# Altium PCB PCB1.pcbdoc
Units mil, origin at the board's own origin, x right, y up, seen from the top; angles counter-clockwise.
Board outline 2864.75 x 3097.61 mil, 2 copper layers (Top Layer, Bottom Layer); 25 components, 23 nets, 126 pads, 0 vias.
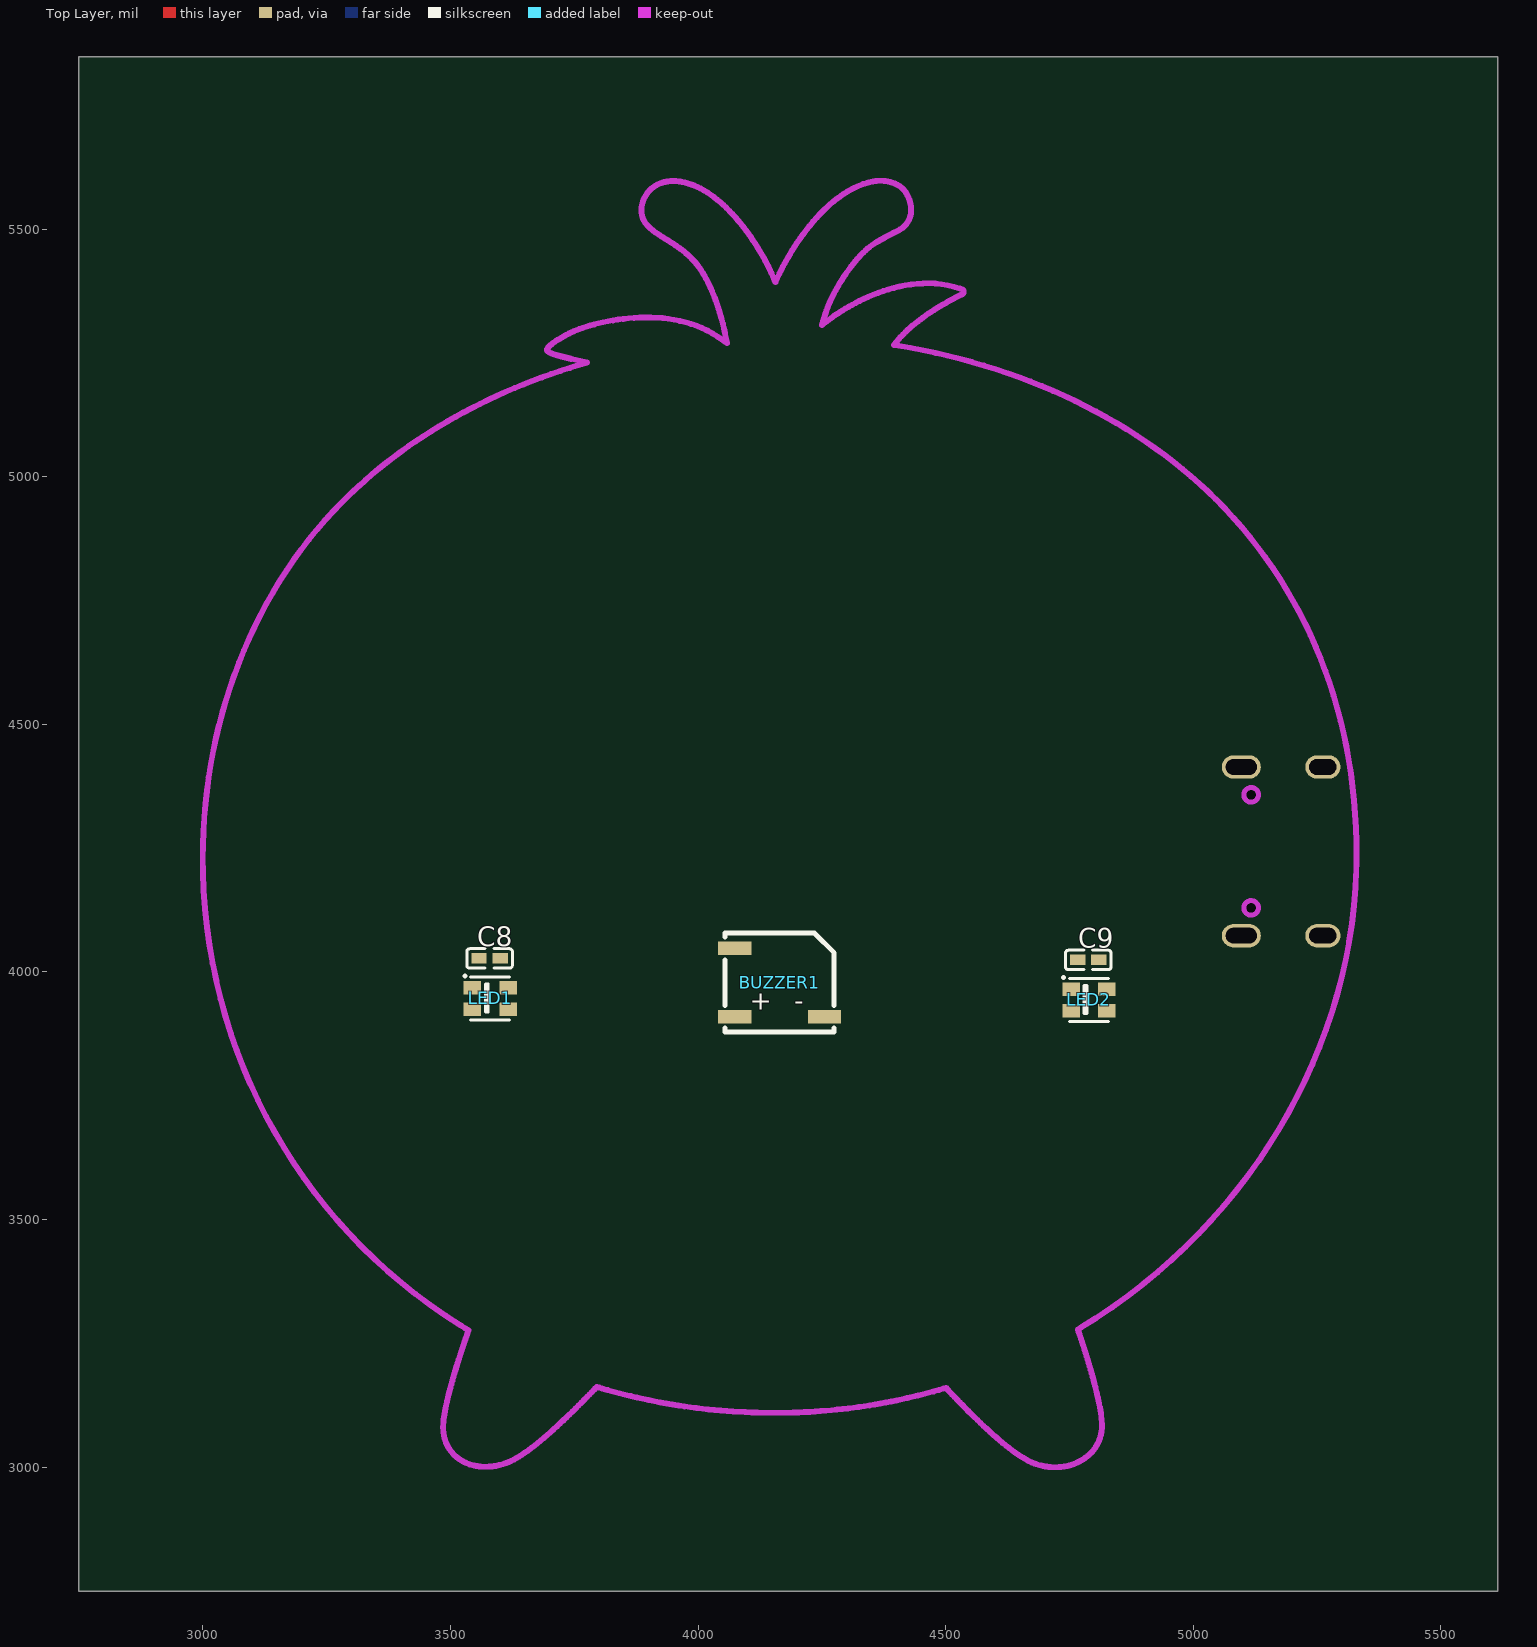
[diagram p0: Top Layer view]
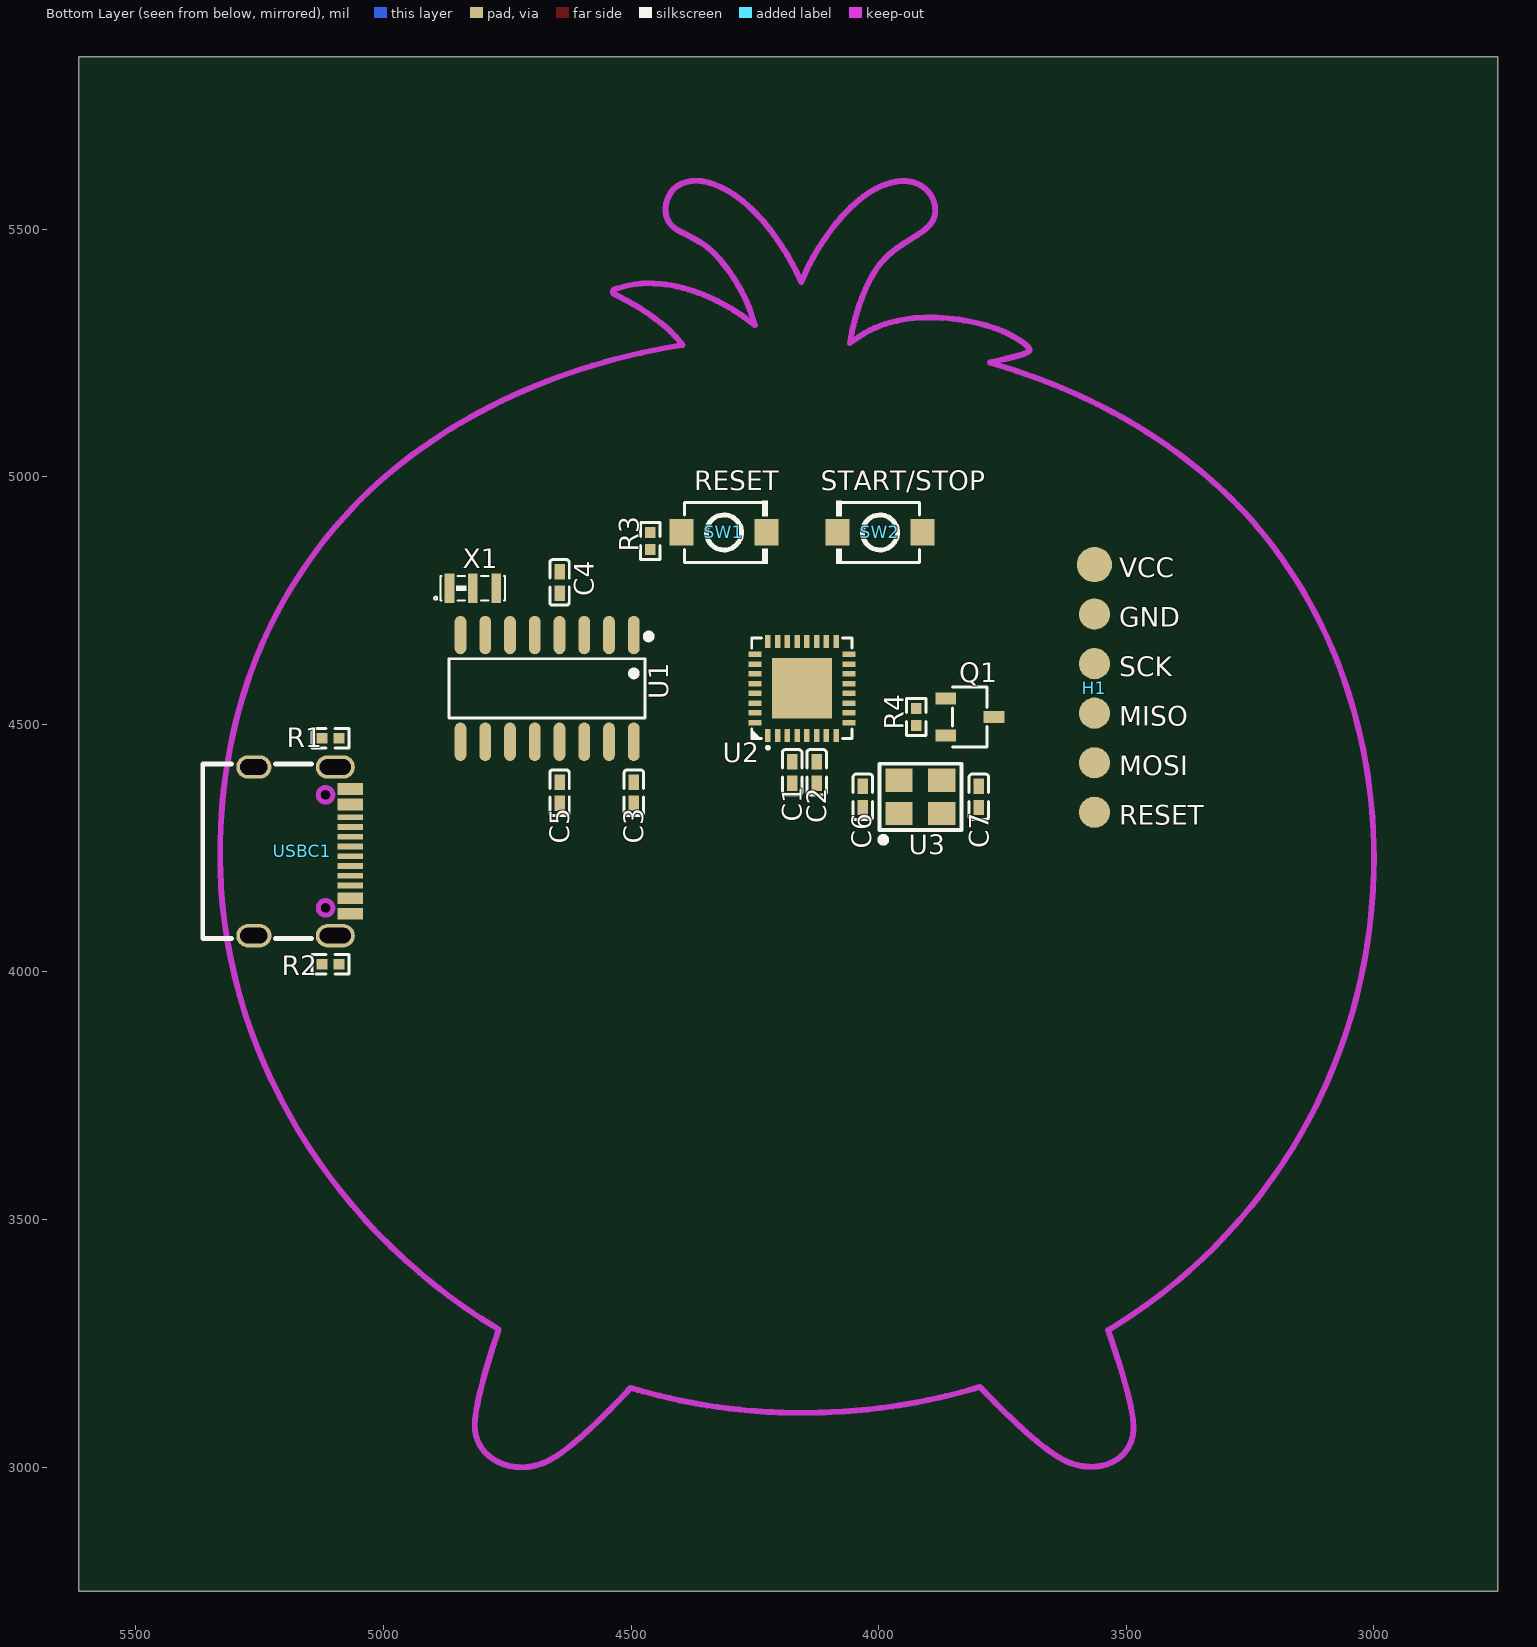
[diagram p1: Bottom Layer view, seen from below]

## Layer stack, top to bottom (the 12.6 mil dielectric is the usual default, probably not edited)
Top Layer: signal copper (thickness not stored)
Dielectric: dielectric 12.6, FR-4, Dk 4.8
Bottom Layer: signal copper (thickness not stored)

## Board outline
5614.75,2750 2750,2750 2750,5847.61 5614.75,5847.61

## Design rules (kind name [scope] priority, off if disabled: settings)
BoardOutlineClearance copperThickness1oz [All] p0: genericclearance=10 ignorepadtopadclearanceinfootprint=FALSE except(0: Arc-SplitContinuation Track-SplitContinuation SMDPad-SplitContinuation THPad-SplitContinuation Via-SplitContinuation Fill-SplitContinuation Poly-SplitContinuation Region-SplitContinuation Text-SplitContinuation; 6: SMDPad-CutoutEdge THPad-CutoutEdge Via-CutoutEdge Fill-CutoutEdge Region-CutoutEdge; 11.8: Track-OutlineEdge SMDPad-OutlineEdge THPad-OutlineEdge Via-OutlineEdge Fill-OutlineEdge Region-OutlineEdge Poly-OutlineEdge Text-OutlineEdge Track-CutoutEdge)
BoardOutlineClearance copperThickness2oz [All] p0: genericclearance=10 ignorepadtopadclearanceinfootprint=FALSE except(0: Arc-SplitContinuation Track-SplitContinuation SMDPad-SplitContinuation THPad-SplitContinuation Via-SplitContinuation Fill-SplitContinuation Poly-SplitContinuation Region-SplitContinuation Text-SplitContinuation; 6: SMDPad-CutoutEdge THPad-CutoutEdge Via-CutoutEdge Fill-CutoutEdge Region-CutoutEdge; 11.8: Track-OutlineEdge SMDPad-OutlineEdge THPad-OutlineEdge Via-OutlineEdge Fill-OutlineEdge Region-OutlineEdge Poly-OutlineEdge Text-OutlineEdge Track-CutoutEdge)
Clearance copperThickness1oz [(InNet('$1N3700') OR InNet('+5V') OR InNet('GND') OR InNet('$1N2036') OR InNet('$1N1921') OR InNet('RESET') OR InNet('XTAL1') OR InNet('XTAL2') OR InNet('MOSI') OR InNet('MISO') OR InNet('SCK') OR InNet('$1N5829') OR InNet('RGB') OR InNet('BUZZER') OR InNet('$1N1307') OR InNet('$1N1311') OR InNet('BT1_PD7') OR InNet('TXD') OR InNet('RXD') OR InNet('D+') OR InNet('D-') OR InNet('$1N4777') OR InNet('$1N4772'))] p1: gap=7 ignorepadtopadclearanceinfootprint=FALSE except(6: Track-SMDPad SMDPad-SMDPad Track-THPad SMDPad-THPad THPad-THPad Track-Via SMDPad-Via THPad-Via Via-Via Track-Fill SMDPad-Fill THPad-Fill Via-Fill Fill-Fill SMDPad-Region THPad-Region Via-Region Fill-Region Region-Region Track-Poly SMDPad-Poly THPad-Poly Via-Poly Fill-Poly Poly-Poly Track-Text SMDPad-Text THPad-Text Via-Text Fill-Text Region-Text Poly-Text Text-Text; 6.9: Track-Hole SMDPad-Hole THPad-Hole Via-Hole Fill-Hole Region-Hole Poly-Hole Text-Hole Sheet-Hole; 7.9: Track-Track; 11.8: Track-Region Region-Poly Track-Sheet SMDPad-Sheet THPad-Sheet Via-Sheet Fill-Sheet Region-Sheet Poly-Sheet Text-Sheet)
Clearance copperThickness2oz [All] p1: gap=7 ignorepadtopadclearanceinfootprint=FALSE except(6: Track-SMDPad SMDPad-SMDPad Track-THPad SMDPad-THPad THPad-THPad Track-Via SMDPad-Via THPad-Via Via-Via Track-Fill SMDPad-Fill THPad-Fill Via-Fill Fill-Fill SMDPad-Region THPad-Region Via-Region Fill-Region Region-Region Track-Poly SMDPad-Poly THPad-Poly Via-Poly Fill-Poly Poly-Poly Track-Text SMDPad-Text THPad-Text Via-Text Fill-Text Region-Text Poly-Text Text-Text; 6.9: Track-Hole SMDPad-Hole THPad-Hole Via-Hole Fill-Hole Region-Hole Poly-Hole Text-Hole Sheet-Hole; 8: Track-Track; 11.8: Track-Region Region-Poly Track-Sheet SMDPad-Sheet THPad-Sheet Via-Sheet Fill-Sheet Region-Sheet Poly-Sheet Text-Sheet)
DiffPairsRouting differentialPair [All] p1: maxuncoupledlength=10 minlimit=5.9843 maxlimit=5.9843 mostfreqgap=5.9843 toplayer_minwidth=5 toplayer_prefwidth=10 toplayer_maxwidth=100 bottomlayer_minwidth=5 bottomlayer_prefwidth=10 bottomlayer_maxwidth=100
PasteMaskExpansion pasteMaskExpansion [All] p1: expansion=0
PlaneConnect innerPlane [All] p1: planeconnectstyle=Relief reliefexpansion=20 reliefentries=4 reliefconductorwidth=10 reliefairgap=10
PolygonConnect copperRegion [All] p1: connectstyle=Relief reliefentries=4 reliefconductorwidth=10 polygonreliefangle="90 Angle" airgapwidth=10
RoutingVias viaSize [All] p1: viastyle="Through Hole" holewidth=11.811 minholewidth=11.811 maxholewidth=248.0314 width=23.622 minwidth=19.685 maxwidth=393.7008
SolderMaskExpansion solderMaskExpansion [All] p1: useseparateexpansions=TRUE expansion=2.0079 expansionbottom=2.0079
Width copperThickness1oz [All] p1: maxlimit=100 minlimit=5 preferedwidth=8
Width copperThickness2oz [All] p1: maxlimit=100 minlimit=8 preferedwidth=10

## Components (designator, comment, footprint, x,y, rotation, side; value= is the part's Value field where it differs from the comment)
BUZZER1 "MLT-5020" BUZ-SMD_L5.0-W5.5-P4.60 4164.82,3978.7 r0 top
C1 "CL05B104KB54PNC" C0402 4174.82,4402.93 r270 bottom
C2 "CL05B104KB54PNC" C0402 4125.29,4402.93 r270 bottom
C3 "CL05B104KB54PNC" C0402 4494.37,4361.93 r90 bottom
C4 "CT41G-0402-2X1-16V-0.1μF-K(N)" C0402 4644.37,4786.55 r90 bottom
C5 "CL05B104KB54PNC" C0402 4644.37,4361.93 r90 bottom
C6 "0402CG220J500NT" C0402 4031.95,4353.49 r270 bottom
C7 "0402CG220J500NT" C0402 3797.69,4353.49 r90 bottom
C8 "CL05B104KB54PNC" C0402 3579.2,4027.33 r180 top
C9 "CL05B104KB54PNC" C0402 4787.98,4024.32 r180 top
H1 "HDR-F_2.54_1x6P" HDR-TH_6P-P2.54-V-F 3564.27,4572.51 r270 bottom
LED1 "WS2812B-2020" LED-SMD_4P-L2.0-W2.0-TL_WS2812B-2020 3580.42,3946.6 r0 top
LED2 "WS2812B-2020" LED-SMD_4P-L2.0-W2.0-TL_WS2812B-2020 4789.2,3943.59 r0 top
Q1 "AO3406_C5379102" SOT-23-3_L2.9-W1.6-P1.90-LS2.8-BR 3815.97,4514.85 r0 bottom
R1 "0402WGF5101TCE" R0402 5107,4471.93 r0 bottom
R2 "0402WGF5101TCE" R0402 5107,4015.24 r0 bottom
R3 "0402WGF100JTCE" R0402 4461.31,4870.43 r270 bottom
R4 "0402WGF5101TCE" R0402 3923.86,4514.85 r90 bottom
SW1 "TS-1088-AR02016" SW-SMD_L3.9-W3.0-P4.45 4312.3,4887.47 r180 bottom
SW2 "TS-1088-AR02016" SW-SMD_L3.9-W3.0-P4.45 3997.34,4887.47 r0 bottom
U1 "CH340G" SOIC-16_L9.9-W3.9-P1.27-LS6.0-BL 4669.37,4572.55 r0 bottom
U2 "ATMEGA328P-MU_C7499261" HVQFN-32_L5.0-W5.0-P0.50-TL-EP3.1 4154.82,4572.51 r90 bottom
U3 "S3216000222080C3" CRYSTAL-SMD_4P-L3.2-W2.5-BL_SIT8008BI 3915.8,4353.49 r180 bottom
USBC1 "TYPE-C-31-M-12" USB-C_SMD-TYPE-C-31-M-12 5164.2,4243.59 r270 bottom
X1 "CSTNE12M0G550000R0" CRYSTAL-SMD_3P-L3.2-W1.3-P1.20-L-1 4819.37,4774.74 r180 bottom

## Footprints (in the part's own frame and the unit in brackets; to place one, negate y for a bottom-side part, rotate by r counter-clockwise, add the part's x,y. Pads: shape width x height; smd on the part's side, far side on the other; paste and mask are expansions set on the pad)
BUZ-SMD_L5.0-W5.5-P4.60 [mm]
  rect 1.7x0.7 smd: 1(-2.3,-1.75) 2(2.3,-1.75) 3(-2.3,1.75)
  silkscreen extent -2.79,-2.54 2.79,2.54
C0402 [mm]
  rect 0.79x0.54 smd: 1(-0.545,0) 2(0.545,0)
  silkscreen extent -1.17,-0.5 1.17,0.5
CRYSTAL-SMD_3P-L3.2-W1.3-P1.20-L-1 [mm]
  rect 0.5x1.5 smd: 1(-1.2,0) 2(0,0) 3(1.2,0)
  silkscreen extent -1.99,-0.64 1.65,0.64
CRYSTAL-SMD_4P-L3.2-W2.5-BL_SIT8008BI [mm]
  rect 1.4x1.2 smd: 1(-1.1,-0.85) 2(1.1,-0.85) 3(1.1,0.85) 4(-1.1,0.85)
  silkscreen extent -2.1,-2.35 2.1,1.7
HDR-TH_6P-P2.54-V-F [mm]
  round 1.8 smd: 1(-6.35,0)
  round 1.6 smd: 2(-3.81,0) 3(-1.27,0) 4(1.27,0) 5(3.81,0) 6(6.35,0)
HVQFN-32_L5.0-W5.0-P0.50-TL-EP3.1 [mm]
  rect 0.665x0.28 smd: 1(-2.407,1.75) 2(-2.407,1.25) 3(-2.407,0.75) 4(-2.407,0.25) 5(-2.407,-0.25) 6(-2.407,-0.75) 7(-2.407,-1.25) 8(-2.407,-1.75) 17(2.407,-1.75) 18(2.407,-1.25) 19(2.407,-0.75) 20(2.407,-0.25) 21(2.407,0.25) 22(2.407,0.75) 23(2.407,1.25) 24(2.407,1.75)
  rect 0.28x0.665 smd: 9(-1.75,-2.407) 10(-1.25,-2.407) 11(-0.75,-2.407) 12(-0.25,-2.407) 13(0.25,-2.407) 14(0.75,-2.407) 15(1.25,-2.407) 16(1.75,-2.407) 25(1.75,2.407) 26(1.25,2.407) 27(0.75,2.407) 28(0.25,2.407) 29(-0.25,2.407) 30(-0.75,2.407) 31(-1.25,2.407) 32(-1.75,2.407)
  rect 3.1x3.1 smd: 33(0,0)
  silkscreen extent -3.11,-2.58 2.58,2.58
LED-SMD_4P-L2.0-W2.0-TL_WS2812B-2020 [mm]
  rect 0.9x0.7 smd: 1(-0.915,0.55) 2(-0.915,-0.55) 3(0.915,-0.55) 4(0.915,0.55)
  silkscreen extent -1.3,-1.1 1,1.15
R0402 [mm]
  rect 0.566x0.54 smd: 1(-0.433,0) 2(0.433,0)
  silkscreen extent -0.94,-0.5 0.94,0.5
SOIC-16_L9.9-W3.9-P1.27-LS6.0-BL [mil]
  oval 23.7x77.6 smd: 1(-175,-107.7) 2(-125,-107.7) 3(-75,-107.7) 4(-25,-107.7) 5(25,-107.7) 6(75,-107.7) 7(125,-107.7) 8(175,-107.7) 9(175,107.7) 10(125,107.7) 11(75,107.7) 12(25,107.7) 13(-25,107.7) 14(-75,107.7) 15(-125,107.7) 16(-175,107.7)
  silkscreen extent -211,-111 198,60
SOT-23-3_L2.9-W1.6-P1.90-LS2.8-BR [mm]
  rect 1.07x0.6 smd: 1(1.235,-0.95) 2(1.235,0.95) 3(-1.235,0)
  silkscreen extent -0.88,-1.54 0.88,1.54
SW-SMD_L3.9-W3.0-P4.45 [mm]
  rect 1.23x1.36 smd: 1(-2.185,0) 2(2.185,0)
  silkscreen extent -2.03,-1.62 2.25,1.62
USB-C_SMD-TYPE-C-31-M-12 [mm]
  oval 1.2x2 hole 0.8 slot 1.6 at 90 deg: 0(-4.325,1.706) 1(4.325,1.706)
  oval 1.2x1.8 hole 0.8 slot 1.4 at 90 deg: 2(4.325,-2.474) 3(-4.325,-2.474)
  rect 0.3x1.3 smd: A1(-3.35,2.474) A4(-2.55,2.474) A5(-1.25,2.474) A6(-0.25,2.474) A7(0.25,2.474) A8(1.25,2.474) A9(2.55,2.474) A12(3.35,2.474) B1(3.05,2.474) B4(2.25,2.474) B5(1.75,2.474) B6(0.75,2.474) B7(-0.75,2.474) B8(-1.75,2.474) B9(-2.25,2.474) B12(-3.05,2.474)
  Board Outline Layer circle w0.005: c-2.9,1.206 r0.375
  Board Outline Layer circle w0.005: c2.9,1.206 r0.375
  Board Outline Layer circle w0.254: c-2.9,1.206 r0.375
  Board Outline Layer circle w0.254: c2.9,1.206 r0.375
  Multi-Layer board cut-out: -2.9,0.831 -3.086,0.882 -3.222,1.019 -3.272,1.206 -3.222,1.392 -3.086,1.529 -2.9,1.581 -2.9,1.581 -2.714,1.529 -2.578,1.392 -2.528,1.206 -2.578,1.019 -2.714,0.882 -2.9,0.831
  Multi-Layer board cut-out: 2.9,0.831 2.714,0.882 2.578,1.019 2.528,1.206 2.578,1.392 2.714,1.529 2.9,1.581 2.9,1.581 3.086,1.529 3.222,1.392 3.272,1.206 3.222,1.019 3.086,0.882 2.9,0.831
  silkscreen extent -4.47,-5.09 4.47,0.49

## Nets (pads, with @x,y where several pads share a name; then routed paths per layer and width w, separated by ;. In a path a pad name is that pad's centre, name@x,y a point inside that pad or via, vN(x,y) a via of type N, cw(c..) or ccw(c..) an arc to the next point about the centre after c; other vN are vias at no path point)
$1N1307: R1.2 USBC1.B5
$1N1311: R2.2 USBC1.A5
$1N1921: C5.2 U1.13
$1N2036: C4.1 U1.4
$1N3700: BUZZER1.2 Q1.3
$1N4772: U1.8 X1.1
$1N4777: U1.7 X1.3
$1N5829: LED1.1 LED2.3
+5V: BUZZER1.1 C1.1 C2.1 C3.2 C8.1 C9.1 H1.1 LED1.4 LED2.4 R3.2 U1.16 U2.4 U2.6 U2.18 USBC1.A4 USBC1.A9 USBC1.B4 USBC1.B9
BT1_PD7: SW2.1 U2.11
BUZZER: Q1.1 R4.2 U2.10
D+: U1.5 USBC1.A6 USBC1.B6
D-: U1.6 USBC1.A7 USBC1.B7
GND: C1.2 C2.2 C3.1 C4.2 C6.1 C7.1 C8.2 C9.2 H1.2 LED1.2 LED2.2 Q1.2 R1.1 R2.1 R4.1 SW1.2 SW2.2 U1.1 U2.3 U2.5 U2.21 U2.33 U3.2 U3.4 USBC1.0 USBC1.1 USBC1.2 USBC1.3 USBC1.A1 USBC1.A12 USBC1.B1 USBC1.B12 X1.2
MISO: H1.4 U2.16
MOSI: H1.5 U2.15
RESET: C5.1 H1.6 R3.1 SW1.1 U2.29
RGB: LED1.3 U2.9
RXD: U1.3 U2.31
SCK: H1.3 U2.17
TXD: U1.2 U2.30
XTAL1: C6.2 U2.7 U3.1
XTAL2: C7.2 U2.8 U3.3
pads on no net: BUZZER1.3 LED2.1 U1.9 U1.10 U1.11 U1.12 U1.14 U1.15 U2.1 U2.2 U2.12 U2.13 U2.14 U2.19 U2.20 U2.22 U2.23 U2.24 U2.25 U2.26 U2.27 U2.28 U2.32 USBC1.A8 USBC1.B8

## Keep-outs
Board Outline Layer:
  lines w11.81: 3536.71,3276.67 3530.61,3280.38 3521.27,3286.13 3489.98,3306.33 3459.51,3327.47 3429.89,3349.53 3401.12,3372.48 3373.23,3396.3 3346.22,3420.96 3320.11,3446.44 3294.91,3472.72 3270.65,3499.76 3247.32,3527.56 3224.95,3556.07 3203.55,3585.28 3183.14,3615.17 3163.72,3645.7 3145.31,3676.85 3127.94,3708.61 3111.6,3740.94 3096.32,3773.82 3082.1,3807.23 3068.97,3841.15 3056.94,3875.53 3046.02,3910.38 3036.22,3945.65 3027.56,3981.32 3020.05,4017.38 3013.72,4053.79 3008.56,4090.54 3004.6,4127.59 3001.85,4164.92 3000.36,4201.15 3000,4228.9 3000.32,4256.56 3001.32,4284.1 3003,4311.52 3005.33,4338.8 3008.33,4365.93 3011.99,4392.88 3016.29,4419.65 3021.24,4446.22 3026.82,4472.57 3033.04,4498.69 3039.89,4524.56 3047.36,4550.18 3055.44,4575.52 3064.14,4600.56 3073.45,4625.31 3083.35,4649.73 3093.86,4673.82 3104.95,4697.55 3116.62,4720.92 3128.88,4743.91 3141.71,4766.5 3155.11,4788.68 3169.07,4810.44 3183.59,4831.76 3198.66,4852.62 3214.28,4873 3230.44,4892.91 3247.14,4912.31 3264.36,4931.2 3276.69,4944.06 3289.21,4956.64 3302.02,4969.02 3315.11,4981.19 3328.47,4993.17 3342.11,5004.94 3356.02,5016.5 3370.19,5027.85 3384.62,5038.99 3399.32,5049.92 3414.26,5060.63 3429.46,5071.12 3444.9,5081.39 3460.58,5091.44 3476.5,5101.26 3492.66,5110.86 3509.05,5120.22 3525.66,5129.35 3542.49,5138.24 3559.54,5146.9 3576.81,5155.31 3594.29,5163.49 3611.97,5171.41 3629.86,5179.1 3647.94,5186.53 3666.22,5193.71 3684.69,5200.63 3703.35,5207.3 3722.19,5213.71 3741.21,5219.86 3744.58,5220.91 3775.58,5230.58 3775.55,5230.6 3743.91,5237.97 3743.33,5238.1 3742.27,5238.35 3741.21,5238.6 3740.16,5238.85 3739.11,5239.1 3738.07,5239.35 3737.03,5239.6 3735.99,5239.86 3734.96,5240.11 3733.94,5240.36 3732.92,5240.62 3731.9,5240.87 3730.89,5241.13 3729.89,5241.38 3728.89,5241.64 3727.89,5241.9 3726.9,5242.15 3725.92,5242.41 3724.94,5242.67 3723.96,5242.92 3722.99,5243.18 3722.03,5243.44 3721.07,5243.7 3720.12,5243.96 3719.18,5244.22 3718.24,5244.48 3717.3,5244.74 3716.37,5245 3715.45,5245.26 3714.53,5245.52 3713.3,5245.87 3711.59,5246.39 3709.98,5246.9 3708.49,5247.41 3707.09,5247.91 3705.8,5248.4 3704.6,5248.89 3703.5,5249.36 3702.48,5249.83 3701.55,5250.29 3700.7,5250.73 3699.93,5251.16 3699.23,5251.58 3698.61,5251.98 3698.05,5252.37 3697.55,5252.74 3697.11,5253.1 3696.72,5253.44 3696.39,5253.75 3696.11,5254.05 3695.87,5254.33 3695.67,5254.58 3695.51,5254.81 3695.38,5255.02 3695.28,5255.2 3695.2,5255.36 3695.15,5255.49 3695.11,5255.59 3695.09,5255.66 3695.08,5255.71 3695.08,5255.73 3695.08,5255.82 3695.09,5255.99 3695.12,5256.22 3695.18,5256.52 3695.29,5256.89 3695.45,5257.34 3695.67,5257.86 3695.98,5258.45 3696.36,5259.11 3696.85,5259.85 3697.45,5260.66 3698.16,5261.55 3699.01,5262.52 3699.99,5263.56 3701.13,5264.68 3702.44,5265.88 3703.91,5267.15 3705.57,5268.51 3707.43,5269.95 3709.5,5271.47 3711.78,5273.07 3714.29,5274.75 3717.04,5276.51 3720.03,5278.36 3723.29,5280.29 3726.83,5282.31 3730.64,5284.41 3734.75,5286.6 3739.16,5288.88 3743.87,5291.23 3748.66,5293.46 3754.14,5295.77 3760.26,5298.14 3766.98,5300.53 3774.28,5302.93 3782.11,5305.29 3790.44,5307.6 3799.24,5309.82 3808.48,5311.94 3818.1,5313.92 3828.09,5315.73 3838.4,5317.35 3849.01,5318.76 3859.87,5319.91 3870.94,5320.8 3882.2,5321.38 3893.61,5321.64 3905.14,5321.53 3916.74,5321.05 3928.38,5320.16 3940.04,5318.83 3951.66,5317.04 3963.23,5314.75 3974.69,5311.95 3986.02,5308.6 3997.18,5304.67 4008.14,5300.15 4018.86,5294.99 4029.31,5289.19 4039.44,5282.7 4040.52,5281.95 4058.4,5269.51 4058.4,5269.54 4054.23,5290.94 4054.16,5291.28 4053.96,5292.3 4053.63,5293.86 4053.19,5295.93 4052.62,5298.49 4051.92,5301.5 4051.1,5304.94 4050.15,5308.77 4049.07,5312.97 4047.86,5317.51 4046.52,5322.35 4045.05,5327.47 4043.44,5332.84 4041.69,5338.43 4039.8,5344.2 4037.78,5350.14 4035.61,5356.21 4033.3,5362.37 4030.84,5368.61 4028.24,5374.89 4025.49,5381.17 4022.59,5387.44 4019.54,5393.67 4016.34,5399.81 4012.99,5405.85 4009.47,5411.76 4005.81,5417.5 4001.98,5423.04 3997.99,5428.36 3993.84,5433.42 3990.66,5437 3988.9,5438.88 3987.12,5440.71 3985.32,5442.51 3983.51,5444.28 3981.67,5446 3979.83,5447.69 3977.97,5449.35 3976.1,5450.97 3974.21,5452.56 3972.32,5454.11 3970.42,5455.64 3968.51,5457.14 3966.59,5458.6 3964.67,5460.05 3962.75,5461.46 3960.82,5462.85 3958.89,5464.21 3956.97,5465.56 3955.04,5466.87 3953.12,5468.17 3951.2,5469.45 3949.29,5470.71 3947.38,5471.95 3945.48,5473.17 3943.59,5474.38 3941.71,5475.57 3939.84,5476.75 3937.98,5477.92 3936.14,5479.07 3934.09,5480.36 3931.46,5482 3928.88,5483.63 3926.34,5485.23 3923.85,5486.83 3921.41,5488.42 3919.03,5490 3916.69,5491.58 3914.42,5493.16 3912.21,5494.75 3910.07,5496.34 3908,5497.95 3906,5499.57 3904.07,5501.21 3902.22,5502.87 3900.45,5504.56 3898.77,5506.27 3897.18,5508.02 3895.67,5509.8 3894.26,5511.62 3892.95,5513.48 3891.73,5515.39 3890.62,5517.34 3889.62,5519.35 3888.72,5521.41 3887.94,5523.53 3887.27,5525.72 3886.73,5527.96 3886.3,5530.28 3886,5532.67 3885.83,5535.07 3885.77,5537.02 3885.79,5538.97 3885.87,5540.91 3886.02,5542.85 3886.24,5544.78 3886.52,5546.7 3886.87,5548.6 3887.28,5550.5 3887.75,5552.38 3888.29,5554.24 3888.88,5556.08 3889.54,5557.9 3890.26,5559.71 3891.03,5561.48 3891.87,5563.24 3892.76,5564.96 3893.71,5566.66 3894.71,5568.33 3895.77,5569.97 3896.88,5571.57 3898.05,5573.14 3899.27,5574.67 3900.54,5576.17 3901.86,5577.62 3903.23,5579.03 3904.65,5580.4 3906.11,5581.73 3907.63,5583 3909.19,5584.23 3910.8,5585.41 3912.87,5586.82 3915.01,5588.14 3917.2,5589.37 3919.45,5590.5 3921.75,5591.55 3924.1,5592.5 3926.5,5593.36 3928.95,5594.13 3931.44,5594.81 3933.98,5595.4 3936.56,5595.89 3939.19,5596.29 3941.86,5596.6 3944.57,5596.82 3947.32,5596.94 3950.11,5596.98 3952.93,5596.92 3955.8,5596.77 3958.69,5596.52 3961.62,5596.19 3964.59,5595.76 3967.58,5595.24 3970.61,5594.63 3973.66,5593.92 3976.74,5593.13 3979.85,5592.24 3982.99,5591.25 3986.15,5590.18 3989.33,5589.01 3992.54,5587.75 3998.73,5585.06 4005.56,5581.68 4012.33,5577.92 4019.02,5573.8 4025.64,5569.34 4032.18,5564.56 4038.63,5559.48 4044.98,5554.14 4051.23,5548.54 4057.37,5542.72 4063.39,5536.69 4069.3,5530.47 4075.07,5524.1 4080.71,5517.59 4086.21,5510.96 4091.57,5504.23 4096.77,5497.44 4101.81,5490.59 4106.68,5483.72 4111.38,5476.84 4115.9,5469.97 4120.24,5463.15 4124.39,5456.39 4128.33,5449.71 4132.08,5443.13 4135.61,5436.69 4138.93,5430.39 4142.02,5424.27 4144.88,5418.34 4147.51,5412.63 4148.37,5410.69 4156.31,5392.63 ; 3536.71,3276.67 3536.71,3276.66 ; 3536.71,3276.66 3534.36,3269.92 3533.78,3268.23 3532.23,3263.74 3530.56,3258.88 3528.8,3253.69 3526.94,3248.19 3525.02,3242.41 3523.02,3236.37 3520.97,3230.1 3518.88,3223.62 3516.76,3216.97 3514.62,3210.17 3512.47,3203.23 3510.32,3196.2 3508.19,3189.09 3506.09,3181.93 3504.02,3174.75 3502,3167.56 3500.05,3160.41 3498.16,3153.31 3496.37,3146.3 3494.66,3139.38 3493.07,3132.6 3491.59,3125.98 3490.24,3119.54 3489.04,3113.31 3487.98,3107.31 3487.09,3101.58 3486.38,3096.13 3485.86,3091 3485.53,3086.2 3485.42,3082.15 3485.44,3079.42 3485.53,3076.73 3485.7,3074.07 3485.95,3071.44 3486.27,3068.84 3486.66,3066.27 3487.13,3063.74 3487.67,3061.24 3488.28,3058.78 3488.96,3056.36 3489.72,3053.97 3490.55,3051.62 3491.44,3049.31 3492.41,3047.04 3493.45,3044.81 3494.56,3042.62 3495.73,3040.48 3496.98,3038.38 3498.29,3036.33 3499.67,3034.32 3501.11,3032.36 3502.63,3030.45 3504.21,3028.58 3505.85,3026.77 3507.56,3025.01 3509.34,3023.3 3511.18,3021.64 3513.08,3020.03 3515.05,3018.48 3517.12,3016.96 3519.64,3015.24 3522.24,3013.61 3524.9,3012.08 3527.63,3010.65 3530.42,3009.32 3533.27,3008.09 3536.17,3006.95 3539.13,3005.91 3542.15,3004.97 3545.21,3004.13 3548.31,3003.39 3551.47,3002.75 3554.66,3002.21 3557.89,3001.76 3561.16,3001.42 3564.46,3001.18 3567.8,3001.04 3571.16,3001 3574.55,3001.06 3577.96,3001.22 3581.39,3001.48 3584.84,3001.85 3588.31,3002.31 3591.79,3002.88 3595.29,3003.55 3598.79,3004.33 3602.29,3005.21 3605.8,3006.18 3609.31,3007.27 3612.82,3008.45 3617.6,3010.31 3622.69,3012.61 3627.99,3015.31 3633.49,3018.39 3639.16,3021.83 3645,3025.6 3650.98,3029.67 3657.09,3034.04 3663.31,3038.67 3669.63,3043.54 3676.02,3048.63 3682.48,3053.92 3688.98,3059.38 3695.52,3065 3702.07,3070.74 3708.61,3076.6 3715.14,3082.53 3721.63,3088.54 3728.06,3094.58 3734.43,3100.64 3740.71,3106.69 3746.89,3112.72 3752.95,3118.7 3758.88,3124.6 3764.66,3130.41 3770.26,3136.11 3775.69,3141.66 3780.91,3147.06 3785.92,3152.27 3790.69,3157.27 3791.73,3158.37 3795.47,3162.3 3795.48,3162.3 3800.68,3160.75 3806.08,3159.15 3817.71,3155.82 3829.38,3152.59 3841.1,3149.48 3852.85,3146.49 3864.64,3143.62 3876.48,3140.86 3888.35,3138.22 3900.26,3135.7 3912.21,3133.29 3924.19,3131 3936.21,3128.82 3948.27,3126.77 3960.36,3124.83 3972.48,3123.01 3984.63,3121.31 3996.82,3119.72 4009.04,3118.26 4021.29,3116.91 4033.57,3115.68 4045.88,3114.57 4058.21,3113.58 4070.58,3112.7 4082.97,3111.95 4095.38,3111.32 4107.83,3110.8 4120.29,3110.4 4132.79,3110.13 4145.3,3109.97 4157.84,3109.93 4169.95,3110.01 4181.08,3110.18 4192.2,3110.45 4203.31,3110.83 4214.41,3111.31 4225.5,3111.89 4236.57,3112.57 4247.64,3113.36 4258.69,3114.25 4269.73,3115.24 4280.75,3116.33 4291.76,3117.52 4302.75,3118.82 4313.73,3120.21 4324.69,3121.71 4335.63,3123.31 4346.55,3125.01 4357.45,3126.81 4368.34,3128.71 4379.2,3130.72 4390.05,3132.82 4400.87,3135.02 4411.66,3137.33 4422.44,3139.74 4433.19,3142.24 4443.92,3144.85 4454.62,3147.55 4465.3,3150.36 4475.95,3153.27 4486.57,3156.27 4495.52,3158.89 4500.8,3160.46 4504.54,3156.42 4508.39,3152.28 4513.16,3147.18 4518.15,3141.89 4523.34,3136.43 4528.72,3130.82 4534.27,3125.08 4539.98,3119.25 4545.83,3113.33 4551.81,3107.35 4557.9,3101.34 4564.08,3095.32 4570.34,3089.3 4576.66,3083.31 4583.03,3077.38 4589.44,3071.52 4595.86,3065.75 4602.28,3060.11 4608.69,3054.61 4615.06,3049.27 4621.39,3044.12 4627.66,3039.18 4633.86,3034.46 4639.96,3030 4645.95,3025.82 4651.82,3021.93 4657.55,3018.37 4663.12,3015.14 4668.52,3012.28 4673.74,3009.8 4678.76,3007.74 4682.72,3006.34 4686.28,3005.21 4689.86,3004.19 4693.44,3003.29 4697.02,3002.49 4700.61,3001.81 4704.19,3001.23 4707.77,3000.77 4711.35,3000.41 4714.91,3000.17 4718.47,3000.03 4722,3000 4725.53,3000.08 4729.03,3000.27 4732.51,3000.56 4735.96,3000.96 4739.39,3001.47 4742.78,3002.09 4746.14,3002.81 4749.47,3003.64 4752.75,3004.57 4756,3005.61 4759.2,3006.76 4762.35,3008 4765.46,3009.36 4768.51,3010.82 4771.51,3012.38 4774.44,3014.04 4777.32,3015.81 4780.14,3017.69 4782.61,3019.45 4784.76,3021.1 4786.85,3022.79 4788.86,3024.53 4790.81,3026.33 4792.69,3028.17 4794.49,3030.05 4796.23,3031.98 4797.89,3033.96 4799.49,3035.97 4801.01,3038.03 4802.46,3040.14 4803.83,3042.28 4805.13,3044.46 4806.36,3046.68 4807.51,3048.94 4808.59,3051.23 4809.59,3053.56 4810.52,3055.92 4811.37,3058.32 4812.14,3060.75 4812.83,3063.21 4813.45,3065.71 4813.98,3068.23 4814.44,3070.78 4814.82,3073.36 4815.12,3075.97 4815.34,3078.6 4815.47,3081.26 4815.53,3083.94 4815.48,3087.39 4815.24,3092.3 4814.81,3097.52 4814.2,3103.03 4813.42,3108.81 4812.48,3114.83 4811.39,3121.06 4810.16,3127.49 4808.81,3134.09 4807.34,3140.82 4805.77,3147.68 4804.1,3154.63 4802.35,3161.66 4800.53,3168.72 4798.64,3175.82 4796.71,3182.9 4794.73,3189.96 4792.73,3196.97 4790.71,3203.91 4788.68,3210.74 4786.65,3217.45 4784.64,3224.01 4782.66,3230.4 4780.71,3236.59 4778.8,3242.56 4776.96,3248.28 4775.18,3253.73 4773.48,3258.89 4771.88,3263.72 4770.37,3268.22 4769.28,3271.45 4767.01,3278.17 4767,3278.19 4773.07,3281.87 4803.36,3300.87 4835.7,3322.6 4867.19,3345.28 4897.82,3368.9 4927.55,3393.41 4956.38,3418.79 4984.28,3445 5011.25,3472.02 5037.25,3499.81 5062.27,3528.34 5086.3,3557.59 5109.31,3587.52 5131.29,3618.1 5152.21,3649.3 5172.07,3681.09 5190.84,3713.44 5208.5,3746.32 5225.04,3779.7 5240.43,3813.55 5254.67,3847.84 5267.72,3882.53 5279.58,3917.6 5290.23,3953.01 5299.64,3988.74 5307.79,4024.76 5314.68,4061.02 5320.28,4097.52 5324.58,4134.2 5327.55,4171.05 5329.17,4208.02 5329.36,4216.96 ; 4156.32,5392.63 4164.52,5410.57 4164.58,5410.72 4165.07,5411.74 4166.03,5413.73 4167.46,5416.63 4169.35,5420.35 4171.7,5424.85 4174.5,5430.05 4177.73,5435.89 4181.4,5442.3 4185.48,5449.23 4189.99,5456.59 4194.9,5464.34 4200.21,5472.4 4205.91,5480.7 4212,5489.19 4218.47,5497.8 4225.3,5506.46 4232.49,5515.1 4240.03,5523.67 4247.92,5532.09 4256.15,5540.31 4264.71,5548.25 4273.58,5555.85 4282.78,5563.04 4292.27,5569.77 4302.07,5575.96 4312.15,5581.55 4322.52,5586.48 4333.16,5590.67 4344.07,5594.07 4353.53,5596.28 4355.85,5596.69 4358.23,5597.02 4360.64,5597.28 4363.09,5597.47 4365.57,5597.58 4368.07,5597.61 4370.59,5597.56 4373.13,5597.43 4375.66,5597.23 4378.2,5596.94 4380.74,5596.57 4383.26,5596.13 4385.76,5595.59 4388.24,5594.98 4390.69,5594.28 4393.11,5593.5 4395.48,5592.63 4397.81,5591.68 4400.09,5590.64 4402.3,5589.51 4404.46,5588.29 4406.54,5586.99 4408.54,5585.59 4410.47,5584.1 4412.3,5582.53 4414.04,5580.86 4415.68,5579.1 4417.22,5577.24 4418.64,5575.29 4419.9,5573.32 4419.93,5573.27 4419.96,5573.22 4419.98,5573.17 4420.01,5573.12 4420.04,5573.08 4420.07,5573.03 4420.09,5572.98 4420.12,5572.93 4420.15,5572.88 4420.18,5572.84 4420.2,5572.79 4420.23,5572.74 4420.26,5572.69 4420.29,5572.65 4420.32,5572.6 4420.34,5572.55 4420.37,5572.5 4420.4,5572.45 4420.43,5572.41 4420.46,5572.36 4420.49,5572.31 4420.51,5572.26 4420.54,5572.22 4420.57,5572.17 4420.6,5572.12 4420.63,5572.07 ; 4156.32,5392.63 4156.31,5392.63 ; 4420.66,5572.03 4420.69,5571.98 4420.72,5571.93 4420.75,5571.88 4421.56,5570.46 4422.43,5568.84 4423.25,5567.22 4424.04,5565.6 4424.77,5563.98 4425.46,5562.36 4426.11,5560.73 4426.71,5559.11 4427.27,5557.49 4427.78,5555.87 4428.25,5554.26 4428.67,5552.65 4429.05,5551.04 4429.38,5549.44 4429.66,5547.84 4429.9,5546.25 4430.09,5544.66 4430.24,5543.08 4430.34,5541.51 4430.39,5539.95 4430.4,5538.4 4430.36,5536.86 4430.27,5535.33 4430.14,5533.81 4429.96,5532.31 4429.73,5530.82 4429.46,5529.34 4429.14,5527.87 4428.77,5526.42 4428.35,5524.98 4427.92,5523.64 4427.45,5522.35 4426.95,5521.08 4426.4,5519.83 4425.82,5518.6 4425.2,5517.38 4424.55,5516.19 4423.85,5515.01 4423.12,5513.86 4422.35,5512.72 4421.54,5511.61 4420.69,5510.51 4419.81,5509.44 4418.88,5508.38 4417.92,5507.34 4416.92,5506.33 4415.89,5505.33 4414.82,5504.36 4413.7,5503.4 4412.56,5502.47 4411.37,5501.55 4410.15,5500.66 4408.89,5499.78 4407.59,5498.93 4406.25,5498.1 4404.88,5497.28 4403.47,5496.49 4402.03,5495.72 4400.55,5494.97 4399.03,5494.24 4397.83,5493.69 4396.91,5493.26 4395.98,5492.82 4395.04,5492.37 4394.11,5491.92 4393.17,5491.46 4392.23,5490.99 4391.29,5490.51 4390.35,5490.03 4389.4,5489.54 4388.45,5489.05 4387.51,5488.56 4386.56,5488.05 4385.61,5487.55 4384.66,5487.04 4383.71,5486.52 4382.75,5486 4381.8,5485.48 4380.85,5484.96 4379.9,5484.43 4378.95,5483.9 4378,5483.37 4377.05,5482.84 4376.1,5482.31 4375.15,5481.78 4374.2,5481.24 4373.26,5480.71 4372.31,5480.17 4371.37,5479.64 4370.43,5479.1 4369.75,5478.72 4369.44,5478.54 4369.13,5478.36 4368.81,5478.19 4368.5,5478.01 4368.19,5477.83 4367.88,5477.66 4367.57,5477.48 4367.26,5477.31 4366.95,5477.13 4366.64,5476.95 4366.33,5476.78 4366.01,5476.6 4365.7,5476.43 4365.39,5476.25 4365.08,5476.08 4364.77,5475.9 4364.46,5475.73 4364.15,5475.55 4363.84,5475.38 4363.53,5475.2 4363.22,5475.03 4362.91,5474.85 4362.6,5474.68 4362.29,5474.51 4361.98,5474.33 4361.67,5474.16 4361.36,5473.99 4361.05,5473.81 4360.74,5473.64 4359.42,5472.9 4355.2,5470.3 4350.95,5467.37 4346.69,5464.14 4342.43,5460.61 4338.17,5456.82 4333.92,5452.77 4329.69,5448.5 4325.49,5444.01 4321.34,5439.34 4317.22,5434.49 4313.17,5429.49 4309.18,5424.36 4305.26,5419.12 4301.42,5413.79 4297.68,5408.38 4294.03,5402.92 4290.49,5397.43 4287.06,5391.92 4283.77,5386.42 4280.6,5380.94 4277.58,5375.51 4274.71,5370.15 4271.99,5364.87 4269.45,5359.69 4267.08,5354.64 4264.9,5349.74 4262.91,5344.99 4261.13,5340.43 4259.55,5336.07 4258.33,5332.35 4250.01,5305.75 4250.08,5305.79 4272.16,5322.67 4272.55,5322.96 4273.79,5323.87 4275.86,5325.35 4278.72,5327.33 4282.35,5329.77 4286.71,5332.62 4291.76,5335.81 4297.49,5339.29 4303.85,5343.02 4310.81,5346.92 4318.35,5350.96 4326.43,5355.07 4335.02,5359.2 4344.09,5363.3 4353.61,5367.3 4363.55,5371.17 4373.87,5374.84 4384.55,5378.26 4395.55,5381.37 4406.84,5384.12 4418.39,5386.46 4430.17,5388.33 4442.15,5389.68 4454.29,5390.44 4466.57,5390.58 4478.95,5390.02 4491.4,5388.73 4503.89,5386.64 4516.39,5383.7 4528.87,5379.86 4533.5,5378.19 4533.68,5378.1 4533.86,5378.01 4534.04,5377.91 4534.21,5377.79 4534.37,5377.67 4534.53,5377.54 4534.69,5377.4 4534.83,5377.25 4534.98,5377.1 4535.11,5376.93 4535.24,5376.76 4535.37,5376.58 4535.48,5376.4 4535.59,5376.21 4535.7,5376.01 4535.79,5375.81 4535.88,5375.6 4535.96,5375.39 4536.04,5375.17 4536.1,5374.95 4536.16,5374.73 4536.21,5374.5 4536.25,5374.27 4536.28,5374.04 4536.3,5373.8 4536.32,5373.56 4536.32,5373.32 4536.32,5373.08 4536.3,5372.84 4536.29,5372.67 4536.28,5372.58 4536.27,5372.49 4536.25,5372.4 4536.24,5372.31 4536.22,5372.22 4536.2,5372.13 4536.18,5372.04 4536.16,5371.95 4536.14,5371.86 4536.11,5371.78 4536.09,5371.69 4536.06,5371.6 4536.03,5371.51 4536,5371.43 4535.97,5371.34 4535.93,5371.25 4535.89,5371.16 4535.85,5371.08 4535.81,5370.99 4535.77,5370.9 4535.73,5370.82 4535.68,5370.73 4535.63,5370.64 4535.58,5370.56 4535.53,5370.47 4535.48,5370.39 4535.42,5370.3 4535.37,5370.21 4535.31,5370.13 4535.25,5370.04 4535.2,5369.97 4535.15,5369.9 4535.09,5369.83 4535.04,5369.76 4534.98,5369.69 4534.92,5369.63 4534.87,5369.56 4534.81,5369.49 4534.75,5369.43 4534.69,5369.37 4534.62,5369.31 4534.56,5369.25 4534.49,5369.19 4534.43,5369.13 4534.36,5369.07 4534.29,5369.01 4534.22,5368.96 4534.15,5368.9 4534.08,5368.85 4534.01,5368.8 4533.94,5368.75 4533.86,5368.7 4533.79,5368.65 4533.71,5368.61 4533.63,5368.56 4533.55,5368.52 4533.47,5368.47 4533.39,5368.43 4533.31,5368.39 4533.08,5368.28 4531.91,5367.72 4530.31,5366.94 4528.3,5365.95 4525.91,5364.75 4523.16,5363.34 4520.07,5361.75 4516.67,5359.96 4512.98,5357.98 4509.02,5355.83 4504.82,5353.5 4500.4,5350.99 4495.78,5348.33 4490.99,5345.5 4486.05,5342.52 4480.99,5339.38 4475.82,5336.11 4470.57,5332.69 4465.26,5329.14 4459.92,5325.46 4454.57,5321.65 4449.23,5317.73 4443.93,5313.69 4438.69,5309.54 4433.53,5305.3 4428.48,5300.95 4423.56,5296.51 4418.79,5291.98 4414.2,5287.37 4409.81,5282.68 4405.71,5278 4395.69,5266.16 4395.73,5266.15 4410.98,5263.55 4429,5260.35 4454.32,5255.46 4479.42,5250.12 4504.31,5244.34 4528.98,5238.12 4553.41,5231.48 4577.59,5224.41 4601.52,5216.92 4625.19,5209.02 4648.58,5200.7 4671.69,5191.98 4694.51,5182.85 4717.03,5173.33 4739.25,5163.41 4761.14,5153.11 4782.71,5142.42 4803.94,5131.35 4824.82,5119.9 4845.35,5108.09 4865.52,5095.9 4885.31,5083.36 4904.72,5070.46 4923.74,5057.2 4942.35,5043.6 4960.56,5029.65 4978.35,5015.37 4995.71,5000.75 5012.63,4985.8 5029.1,4970.52 5045.12,4954.93 5062.28,4937.34 5080.18,4918 5097.47,4898.26 5114.16,4878.12 5130.25,4857.59 5145.74,4836.67 5160.61,4815.37 5174.88,4793.7 5188.53,4771.66 5201.56,4749.25 5213.98,4726.49 5225.78,4703.38 5236.95,4679.92 5247.5,4656.13 5257.43,4632 5266.72,4607.55 5275.39,4582.77 5283.42,4557.68 5290.81,4532.28 5297.57,4506.58 5303.68,4480.58 5309.15,4454.29 5313.98,4427.72 5318.16,4400.86 5321.7,4373.74 5324.57,4346.34 5326.8,4318.69 5328.37,4290.78 5329.28,4262.62 5329.53,4234.22 5329.36,4216.97 ; 4420.66,5572.03 4420.63,5572.07 ; 5329.36,4216.96 5329.36,4216.97

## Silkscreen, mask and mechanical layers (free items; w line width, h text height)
Bottom Silkscreen Layer:
  text "START/STOP" at 4117.34,4972.47 h39.37
  text "RESET" at 4372.3,4972.47 h39.37
  text "VCC" at 3514.27,4797.51 h39.37
  text "GND" at 3514.27,4697.51 h39.37
  text "SCK" at 3514.27,4597.51 h39.37
  text "MISO" at 3514.27,4497.51 h39.37
  text "MOSI" at 3514.27,4397.51 h39.37
  text "RESET" at 3514.27,4297.51 h39.37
